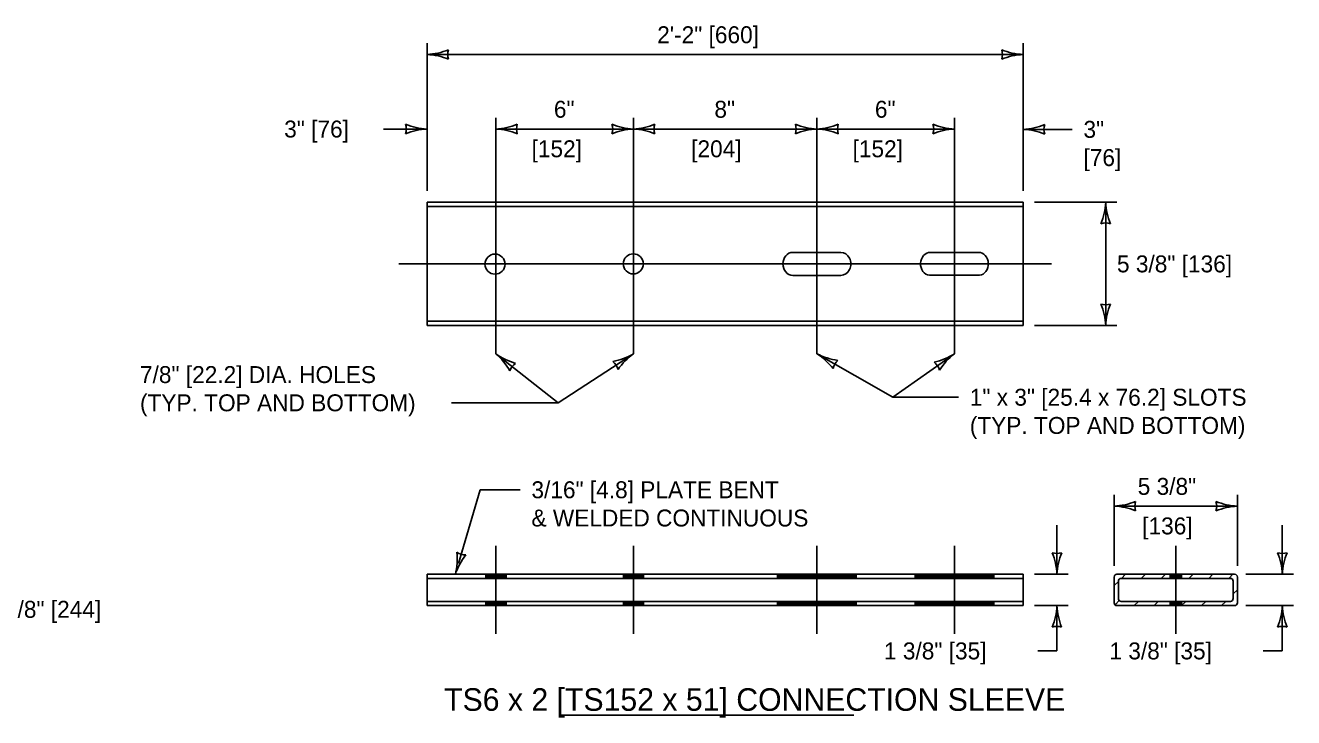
# Model space of a CAD drawing. Extents: x 49991.4 to 50021, y 49987.6 to 50011.4.
# Drawn here: x 50005.864 to 50010.355, y 49990.69 to 49993.141 of the extents above; entities that cross this region are included whole.
import ezdxf

# ---------------------------------------------------------------- set-up
doc = ezdxf.new("R2010")
doc.units = 0
for name, color, linetype in [('Level 1', 7, 'Continuous'), ('Level 2', 7, 'Continuous'), ('Level 3', 7, 'Continuous'), ('Level 4', 7, 'Continuous'), ('Level 5', 7, 'Continuous')]:
    doc.layers.add(name, color=color, linetype=linetype)

msp = doc.modelspace()

# ---------------------------------------------------------------- linework, layer by layer
at = {"layer": 'Level 1'}
for p, q in [((50007.2867, 49992.515), (50009.3979, 49992.515)), ((50007.2867, 49992.0782), (50007.2867, 49992.515)), ((50009.3979, 49992.0782), (50009.3979, 49992.515)), ((50008.5818, 49992.3372), (50008.7521, 49992.3372)), ((50009.069, 49992.3372), (50009.2393, 49992.3372)), ((50008.5818, 49992.256), (50008.7521, 49992.256)), ((50009.0653, 49992.2562), (50009.2429, 49992.2562)), ((50007.2867, 49992.0782), (50009.3979, 49992.0782)), ((50007.2867, 49991.1976), (50009.3979, 49991.1976)), ((50007.2867, 49991.0864), (50007.2867, 49991.1976)), ((50007.4947, 49991.1922), (50007.5663, 49991.1922)), ((50007.4947, 49991.1874), (50007.5663, 49991.1874)), ((50008.0535, 49991.1922), (50007.9819, 49991.1922)), ((50008.0535, 49991.1874), (50007.9819, 49991.1874)), ((50008.5275, 49991.1922), (50008.8067, 49991.1922)), ((50008.5275, 49991.1874), (50008.8067, 49991.1874)), ((50009.2939, 49991.1922), (50009.0147, 49991.1922)), ((50009.2939, 49991.1874), (50009.0147, 49991.1874)), ((50009.3979, 49991.0864), (50009.3979, 49991.1976)), ((50009.7197, 49991.0964), (50009.7197, 49991.1876)), ((50009.7197, 49991.1572), (50009.7347, 49991.1722)), ((50010.1463, 49991.1976), (50009.7297, 49991.1976)), ((50009.7347, 49991.1114), (50009.7347, 49991.1726)), ((50010.1313, 49991.1826), (50009.7447, 49991.1826)), ((50009.7452, 49991.1826), (50009.7602, 49991.1976)), ((50009.8159, 49991.1826), (50009.8309, 49991.1976)), ((50009.8866, 49991.1826), (50009.9016, 49991.1976)), ((50009.9181, 49991.1922), (50009.9585, 49991.1922)), ((50009.9181, 49991.1874), (50009.9585, 49991.1874)), ((50010.1463, 49991.1976), (50009.9585, 49991.1976)), ((50009.984, 49991.1826), (50009.999, 49991.1976)), ((50010.0547, 49991.1826), (50010.0697, 49991.1976)), ((50010.1254, 49991.1826), (50010.1404, 49991.1976)), ((50010.1413, 49991.1114), (50010.1413, 49991.1726)), ((50010.1413, 49991.1726), (50010.1413, 49991.1114)), ((50010.1563, 49991.0964), (50010.1563, 49991.1876)), ((50010.1563, 49991.0964), (50010.1563, 49991.1876)), ((50010.1413, 49991.1278), (50010.1563, 49991.1428)), ((50007.2867, 49991.0864), (50009.3979, 49991.0864)), ((50007.4947, 49991.0966), (50007.5663, 49991.0966)), ((50007.4947, 49991.0912), (50007.5663, 49991.0912)), ((50008.0535, 49991.0966), (50007.9819, 49991.0966)), ((50008.0535, 49991.0912), (50007.9819, 49991.0912)), ((50008.5275, 49991.0966), (50008.8067, 49991.0966)), ((50008.5275, 49991.0912), (50008.8067, 49991.0912)), ((50009.2939, 49991.0966), (50009.0147, 49991.0966)), ((50009.2939, 49991.0912), (50009.0147, 49991.0912)), ((50009.7229, 49991.0896), (50009.7376, 49991.1044)), ((50010.1463, 49991.0864), (50009.7297, 49991.0864)), ((50010.1313, 49991.1014), (50009.7447, 49991.1014)), ((50009.7904, 49991.0864), (50009.8054, 49991.1014)), ((50009.8611, 49991.0864), (50009.8761, 49991.1014)), ((50009.9181, 49991.0966), (50009.9585, 49991.0966)), ((50009.9181, 49991.0912), (50009.9585, 49991.0912)), ((50009.9585, 49991.0865), (50009.9735, 49991.1014)), ((50009.9585, 49991.0864), (50010.1463, 49991.0864)), ((50010.0292, 49991.0864), (50010.0442, 49991.1014)), ((50010.0999, 49991.0864), (50010.1149, 49991.1014))]:
    msp.add_line(p, q, dxfattribs=at)
for centre in [(50007.5272, 49992.2957), (50008.0169, 49992.2966)]:
    msp.add_circle(centre, 0.0356, dxfattribs=at)
for centre, start, end in [((50009.7297, 49991.1876), 90, 180), ((50009.7447, 49991.1726), 90, 180), ((50010.1313, 49991.1726), 0, 90), ((50010.1313, 49991.1726), 0, 90), ((50010.1463, 49991.1876), 0, 90), ((50010.1463, 49991.1876), 0, 90), ((50009.7447, 49991.1114), 180, 270), ((50010.1313, 49991.1114), 270, 0), ((50010.1313, 49991.1114), 270, 0), ((50009.7297, 49991.0964), 180, 270), ((50010.1463, 49991.0964), 270, 0), ((50010.1463, 49991.0964), 270, 0)]:
    msp.add_arc(centre, 0.01, start, end, dxfattribs=at)
for centre, start_param, end_param in [((50008.5818, 49992.2966), 3.141593, 6.283185), ((50008.7521, 49992.2966), 0, 3.141593), ((50009.069, 49992.2966), 3.141593, 6.178415), ((50009.2393, 49992.2966), 0.10477, 3.141593)]:
    msp.add_ellipse(centre, major_axis=(0, -0.0406), ratio=0.858429, start_param=start_param, end_param=end_param, dxfattribs=at)
at = {"layer": 'Level 2'}
msp.add_line((50007.7538, 49990.6978), (50008.7984, 49990.6978), dxfattribs=at)
at = {"layer": 'Level 3'}
for p, q in [((50007.2865, 49992.555), (50007.2865, 49993.0782)), ((50009.3977, 49992.555), (50009.3977, 49993.0782)), ((50007.2865, 49993.0382), (50009.3977, 49993.0382)), ((50007.1317, 49992.7742), (50007.2865, 49992.7742)), ((50007.5301, 49992.7742), (50008.0173, 49992.7742)), ((50008.6669, 49992.7742), (50008.0173, 49992.7742)), ((50009.1541, 49992.7742), (50008.6669, 49992.7742)), ((50009.5711, 49992.7731), (50009.3977, 49992.7731)), ((50009.4379, 49992.515), (50009.7297, 49992.515)), ((50009.6897, 49992.515), (50009.6897, 49992.0783)), ((50009.4379, 49992.0783), (50009.7297, 49992.0783)), ((50007.5301, 49991.9782), (50007.7504, 49991.8046)), ((50008.0173, 49991.9782), (50007.7504, 49991.8046)), ((50008.6669, 49991.9782), (50008.9354, 49991.8244)), ((50009.1541, 49991.9782), (50008.9354, 49991.8244)), ((50007.7504, 49991.8046), (50007.3736, 49991.8046)), ((50008.9354, 49991.8244), (50009.1685, 49991.8244)), ((50007.3976, 49991.235), (50007.4741, 49991.4966)), ((50007.4741, 49991.4966), (50007.6162, 49991.4966)), ((50009.7195, 49991.2276), (50009.7195, 49991.4786)), ((50010.1562, 49991.2276), (50010.1562, 49991.4786)), ((50010.1562, 49991.4386), (50009.7195, 49991.4386)), ((50009.517, 49991.1977), (50009.517, 49991.3711)), ((50010.3153, 49991.1977), (50010.3153, 49991.3711)), ((50009.4379, 49991.1977), (50009.557, 49991.1977)), ((50010.1863, 49991.1977), (50010.3553, 49991.1977)), ((50009.4379, 49991.0864), (50009.557, 49991.0864)), ((50009.517, 49991.0864), (50009.517, 49990.9259)), ((50010.1863, 49991.0864), (50010.3553, 49991.0864)), ((50010.3153, 49991.0864), (50010.3153, 49990.9259)), ((50009.4492, 49990.9259), (50009.517, 49990.9259)), ((50010.2475, 49990.9259), (50010.3153, 49990.9259))]:
    msp.add_line(p, q, dxfattribs=at)
for centre, radius, start, end in [((50007.275, 49993.2709), 0.233, 272.8273, 292.0772), ((50007.4147, 49993.0382), 0.0548, 162.1388, 197.8612), ((50009.4069, 49993.2603), 0.2223, 247.456, 267.6395), ((50009.2695, 49993.0382), 0.0548, 342.1388, 17.8612), ((50007.2774, 49992.8161), 0.2223, 67.456, 87.6395), ((50009.4092, 49992.8055), 0.233, 92.8273, 112.0772), ((50007.2957, 49992.9963), 0.2223, 247.456, 267.6395), ((50007.1583, 49992.7742), 0.0548, 342.1388, 17.8612), ((50007.298, 49992.5414), 0.233, 92.8273, 112.0772), ((50007.5186, 49993.0069), 0.233, 272.8273, 292.0772), ((50007.521, 49992.5521), 0.2223, 67.456, 87.6395), ((50007.6583, 49992.7742), 0.0548, 162.1388, 197.8612), ((50008.0265, 49992.9963), 0.2223, 247.456, 267.6395), ((50007.8891, 49992.7742), 0.0548, 342.1388, 17.8612), ((50008.0288, 49992.5415), 0.233, 92.8273, 112.0772), ((50008.0058, 49993.0069), 0.233, 272.8273, 292.0772), ((50008.0082, 49992.5521), 0.2223, 67.456, 87.6395), ((50008.1455, 49992.7742), 0.0548, 162.1388, 197.8612), ((50008.6761, 49992.9963), 0.2223, 247.456, 267.6395), ((50008.5387, 49992.7742), 0.0548, 342.1388, 17.8612), ((50008.6784, 49992.5415), 0.233, 92.8273, 112.0772), ((50008.6554, 49993.0069), 0.233, 272.8273, 292.0772), ((50008.6578, 49992.5521), 0.2223, 67.456, 87.6395), ((50008.7951, 49992.7742), 0.0548, 162.1388, 197.8612), ((50009.1633, 49992.9963), 0.2223, 247.456, 267.6395), ((50009.0259, 49992.7742), 0.0548, 342.1388, 17.8612), ((50009.1656, 49992.5415), 0.233, 92.8273, 112.0772), ((50009.3862, 49993.0058), 0.233, 272.8273, 292.0772), ((50009.3886, 49992.5509), 0.2223, 67.456, 87.6395), ((50009.5259, 49992.7731), 0.0548, 162.1388, 197.8612), ((50009.4676, 49992.5241), 0.2223, 337.456, 357.6395), ((50009.9224, 49992.5264), 0.233, 182.8273, 202.0772), ((50009.6897, 49992.3867), 0.0548, 72.1388, 107.8612), ((50009.6897, 49992.2065), 0.0548, 252.1388, 287.8612), ((50009.457, 49992.0668), 0.233, 2.8273, 22.0772), ((50009.9119, 49992.0691), 0.2223, 157.456, 177.6395), ((50007.3854, 49991.8094), 0.2223, 29.2052, 49.3887), ((50007.6652, 49992.1681), 0.233, 234.5765, 253.8263), ((50007.9039, 49992.1694), 0.2223, 280.5006, 300.6841), ((50008.1539, 49991.7894), 0.233, 125.8719, 145.1218), ((50008.5486, 49991.79), 0.2223, 37.6518, 57.8353), ((50008.7726, 49992.1859), 0.233, 243.0231, 262.273), ((50009.0338, 49992.1652), 0.2223, 282.5755, 302.759), ((50009.2974, 49991.7945), 0.233, 127.9468, 147.1967), ((50007.6308, 49991.8988), 0.0548, 123.888, 159.6104), ((50007.9099, 49991.9083), 0.0548, 15.1834, 50.9058), ((50008.7782, 49991.9145), 0.0548, 132.3346, 168.057), ((50009.0493, 49991.9044), 0.0548, 17.2583, 52.9807), ((50009.708, 49991.6713), 0.233, 272.8273, 292.0772), ((50009.7104, 49991.2165), 0.2223, 67.456, 87.6395), ((50009.8477, 49991.4386), 0.0548, 162.1388, 197.8612), ((50010.1654, 49991.6607), 0.2223, 247.456, 267.6395), ((50010.028, 49991.4386), 0.0548, 342.1388, 17.8612), ((50010.1677, 49991.2059), 0.233, 92.8273, 112.0772), ((50007.1601, 49991.2519), 0.233, 346.5192, 5.769), ((50007.5973, 49991.1264), 0.2223, 141.1479, 161.3314), ((50007.4226, 49991.3207), 0.0548, 235.8307, 271.5531), ((50009.517, 49991.3259), 0.0548, 252.1388, 287.8612), ((50009.2843, 49991.1862), 0.233, 2.8273, 22.0772), ((50009.7392, 49991.1885), 0.2223, 157.456, 177.6395), ((50010.3153, 49991.3259), 0.0548, 252.1388, 287.8612), ((50010.0826, 49991.1862), 0.233, 2.8273, 22.0772), ((50010.5375, 49991.1885), 0.2223, 157.456, 177.6395), ((50009.2949, 49991.0955), 0.2223, 337.456, 357.6395), ((50009.7497, 49991.0978), 0.233, 182.8273, 202.0772), ((50010.0932, 49991.0955), 0.2223, 337.456, 357.6395), ((50010.548, 49991.0978), 0.233, 182.8273, 202.0772), ((50009.517, 49990.9581), 0.0548, 72.1388, 107.8612), ((50010.3153, 49990.9581), 0.0548, 72.1388, 107.8612)]:
    msp.add_arc(centre, radius, start, end, dxfattribs=at)
at = {"layer": 'Level 4'}
for p, q in [((50009.3979, 49992.5), (50007.2867, 49992.5)), ((50009.3979, 49992.0932), (50007.2867, 49992.0932)), ((50009.3979, 49991.1826), (50007.2867, 49991.1826)), ((50007.4947, 49991.1976), (50007.4947, 49991.1826)), ((50007.5663, 49991.1826), (50007.5663, 49991.1976)), ((50007.9819, 49991.1826), (50007.9819, 49991.1976)), ((50008.0535, 49991.1976), (50008.0535, 49991.1826)), ((50008.5275, 49991.1826), (50008.5275, 49991.1976)), ((50008.8067, 49991.1976), (50008.8067, 49991.1826)), ((50009.0147, 49991.1976), (50009.0147, 49991.1826)), ((50009.2939, 49991.1826), (50009.2939, 49991.1976)), ((50009.9181, 49991.1826), (50009.9181, 49991.1976)), ((50009.9585, 49991.1976), (50009.9585, 49991.1826)), ((50009.3979, 49991.1014), (50007.2867, 49991.1014)), ((50007.4947, 49991.0864), (50007.4947, 49991.1014)), ((50007.5663, 49991.1014), (50007.5663, 49991.0864)), ((50007.9819, 49991.1014), (50007.9819, 49991.0864)), ((50008.0535, 49991.0864), (50008.0535, 49991.1014)), ((50008.5275, 49991.1014), (50008.5275, 49991.0864)), ((50008.8067, 49991.0864), (50008.8067, 49991.1014)), ((50009.0147, 49991.0864), (50009.0147, 49991.1014)), ((50009.2939, 49991.1014), (50009.2939, 49991.0864)), ((50009.9181, 49991.1014), (50009.9181, 49991.0864)), ((50009.9585, 49991.0864), (50009.9585, 49991.1014))]:
    msp.add_line(p, q, dxfattribs=at)
at = {"layer": 'Level 5'}
for p, q in [((50007.5301, 49991.9782), (50007.5301, 49992.8142)), ((50008.0173, 49991.9782), (50008.0173, 49992.8142)), ((50008.6669, 49991.9782), (50008.6669, 49992.8142)), ((50009.1541, 49991.9782), (50009.1541, 49992.8142)), ((50007.1867, 49992.2966), (50009.4979, 49992.2966)), ((50007.5303, 49991.2976), (50007.5303, 49990.9864)), ((50008.0175, 49991.2976), (50008.0175, 49990.9864)), ((50008.6671, 49991.2976), (50008.6671, 49990.9864)), ((50009.1543, 49991.2976), (50009.1543, 49990.9864)), ((50009.9387, 49990.9864), (50009.9387, 49991.2976))]:
    msp.add_line(p, q, dxfattribs=at)

# ---------------------------------------------------------------- texts
at = {"layer": 'Level 2'}
for s, height, p in [('2\'-2" [660]', 0.06, (50008.1015, 49993.0782)), ('6"', 0.06, (50007.7357, 49992.8142)), ('8"', 0.06, (50008.3041, 49992.8142)), ('6"', 0.06, (50008.8725, 49992.8142)), ('3" [76]', 0.06, (50006.7806, 49992.7442)), ('3"', 0.06, (50009.6111, 49992.7431)), ('[152]', 0.06, (50007.6566, 49992.6742)), ('[204]', 0.06, (50008.2219, 49992.6742)), ('[152]', 0.06, (50008.7934, 49992.6742)), ('[76]', 0.06, (50009.6111, 49992.6431)), ('5 3/8" [136]', 0.06, (50009.7297, 49992.2666)), ('7/8" [22.2] DIA. HOLES ', 0.06, (50006.2699, 49991.8746)), ('(TYP. TOP AND BOTTOM)', 0.06, (50006.2699, 49991.7746)), ('1" x 3" [25.4 x 76.2] SLOTS', 0.06, (50009.2085, 49991.7944)), ('(TYP. TOP AND BOTTOM)', 0.06, (50009.2085, 49991.6944)), ('3/16" [4.8] PLATE BENT', 0.06, (50007.6562, 49991.4666)), ('5 3/8"', 0.06, (50009.8032, 49991.4786)), ('& WELDED CONTINUOUS', 0.06, (50007.6562, 49991.3666)), ('[136]', 0.06, (50009.8191, 49991.3386)), ('9 5/8" [244]', 0.06, (50005.7249, 49991.0432)), ('1 3/8" [35]', 0.06, (50008.9046, 49990.8959)), ('1 3/8" [35]', 0.06, (50009.7029, 49990.8959)), ('TS6 x 2 [TS152 x 51] CONNECTION SLEEVE', 0.08, (50007.3469, 49990.7137))]:
    msp.add_text(s, height=height, dxfattribs=at).set_placement(p)

doc.saveas('drawing.dxf')
